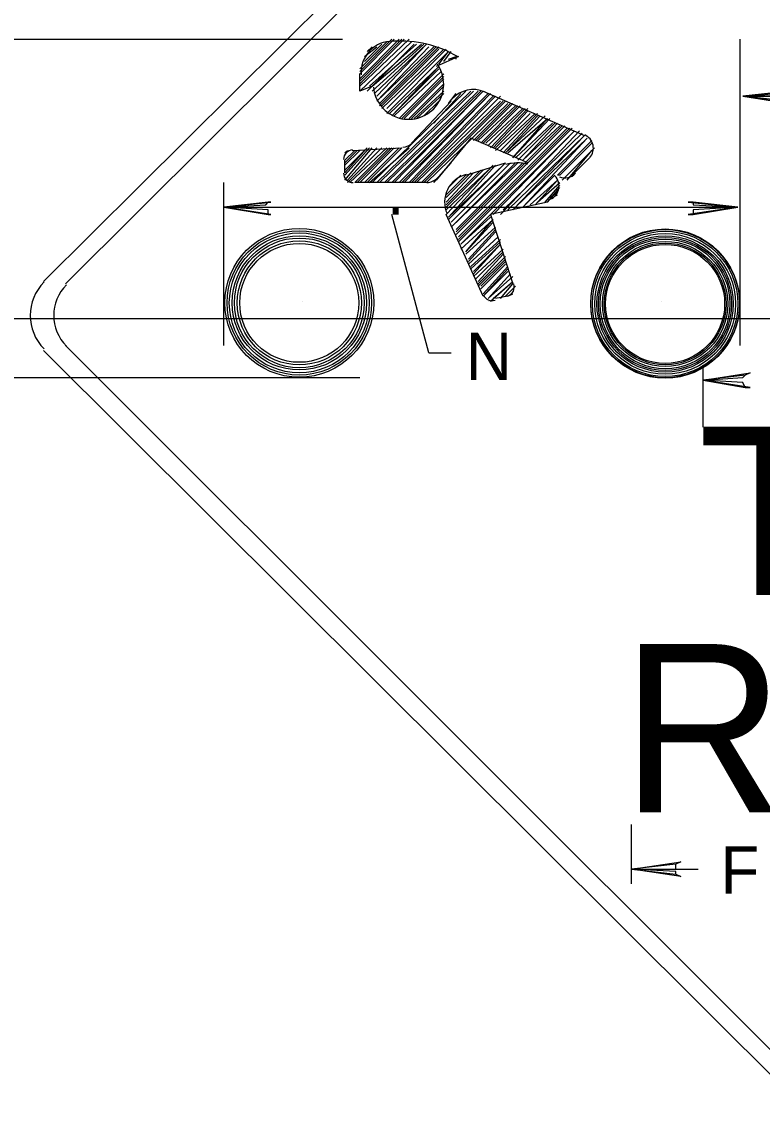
# Model space of a CAD drawing. Extents: x -0.018 to 0.195, y -0.006 to 0.263.
# Drawn here: x 0.0462 to 0.0836, y 0.1098 to 0.1654 of the extents above; entities that cross this region are included whole.
import ezdxf

# ---------------------------------------------------------------- set-up
doc = ezdxf.new("R2010")
doc.units = 0
doc.layers.add('1', color=7, linetype='Continuous')
doc.layers.add('12', color=7, linetype='Continuous')

msp = doc.modelspace()

# ---------------------------------------------------------------- linework, layer by layer
at = {"layer": '1'}
for p, q in [((0.043625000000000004, 0.1645), (0.062375, 0.1645)), ((0.056375, 0.149), (0.056375, 0.15725)), ((0.056375, 0.156), (0.082375, 0.156)), ((0.032375, 0.150375), (0.143125, 0.150375)), ((0.025750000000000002, 0.147375), (0.06325, 0.147375))]:
    msp.add_line(p, q, dxfattribs=at)
msp.add_lwpolyline([(0.058625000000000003, 0.155625), (0.058625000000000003, 0.155875), (0.056375, 0.156), (0.058625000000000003, 0.155625), (0.058750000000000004, 0.155625), (0.056375, 0.156), (0.0585, 0.156125), (0.058625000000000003, 0.15625), (0.056375, 0.156), (0.058750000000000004, 0.15625), (0.058625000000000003, 0.15625)], dxfattribs=at)
at = {"layer": '12'}
for p, q in [((0.04725, 0.15225), (0.08637500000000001, 0.19112500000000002)), ((0.048375, 0.152125), (0.08650000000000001, 0.19012500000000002)), ((0.06325, 0.162875), (0.064875, 0.1645)), ((0.06325, 0.16275), (0.065, 0.1645)), ((0.06325, 0.1625), (0.06525, 0.1645)), ((0.06325, 0.162375), (0.065375, 0.1645)), ((0.06325, 0.16225), (0.0655, 0.1645)), ((0.06325, 0.162125), (0.06575, 0.1645)), ((0.06325, 0.163), (0.064625, 0.164375)), ((0.06325, 0.161875), (0.065875, 0.164375)), ((0.0635, 0.163375), (0.064375, 0.16425)), ((0.0635, 0.163625), (0.064125, 0.164125)), ((0.063625, 0.161875), (0.066, 0.16425)), ((0.063625, 0.163875), (0.063875, 0.164125)), ((0.06375, 0.162125), (0.066125, 0.16425)), ((0.063875, 0.162125), (0.066375, 0.16425)), ((0.063875, 0.161875), (0.0665, 0.16425)), ((0.064, 0.16175), (0.066625, 0.16425)), ((0.064125, 0.161625), (0.066625, 0.16425)), ((0.064125, 0.161375), (0.06675, 0.164125)), ((0.064125, 0.161375), (0.067, 0.164125)), ((0.06425, 0.16125), (0.067125, 0.164125)), ((0.06425, 0.161125), (0.06725, 0.164125)), ((0.0825, 0.149), (0.0825, 0.1645)), ((0.064375, 0.161125), (0.06725, 0.164)), ((0.064375, 0.161), (0.0675, 0.164)), ((0.064625, 0.161), (0.067625, 0.164)), ((0.064625, 0.16075), (0.06775, 0.163875)), ((0.06825, 0.163625), (0.067125, 0.163125)), ((0.06725, 0.16325), (0.06775, 0.163875)), ((0.0675, 0.163375), (0.067875, 0.163875)), ((0.06775, 0.1635), (0.068125, 0.163625)), ((0.068125, 0.163625), (0.06825, 0.163625)), ((0.068125, 0.1635), (0.068125, 0.163625)), ((0.06475, 0.16075), (0.06725, 0.163125)), ((0.064875, 0.160625), (0.06725, 0.163125)), ((0.064875, 0.160625), (0.06725, 0.163)), ((0.06325, 0.161875), (0.06325, 0.16275)), ((0.065, 0.160625), (0.067375, 0.162875)), ((0.06525, 0.1605), (0.0675, 0.16275)), ((0.065375, 0.1605), (0.0675, 0.162625)), ((0.0655, 0.1605), (0.0675, 0.1625)), ((0.063875, 0.162125), (0.06325, 0.161875)), ((0.063875, 0.15725), (0.068625, 0.161875)), ((0.064125, 0.15725), (0.068875, 0.161875)), ((0.06425, 0.15725), (0.069, 0.161875)), ((0.0645, 0.15725), (0.06925, 0.161875)), ((0.064625, 0.15725), (0.069375, 0.161875)), ((0.064875, 0.15725), (0.0695, 0.161875)), ((0.065, 0.15725), (0.0695, 0.161875)), ((0.06575, 0.1605), (0.0675, 0.16225)), ((0.065875, 0.1605), (0.0675, 0.162125)), ((0.066, 0.1605), (0.0675, 0.161875)), ((0.0695, 0.161875), (0.074625, 0.15962500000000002)), ((0.06525, 0.15725), (0.06975, 0.16175)), ((0.065375, 0.15725), (0.069875, 0.16175)), ((0.0655, 0.15725), (0.069875, 0.16175)), ((0.06575, 0.15725), (0.07, 0.161625)), ((0.065875, 0.15725), (0.070125, 0.161625)), ((0.065875, 0.15925), (0.067875, 0.161375)), ((0.066, 0.15725), (0.07037500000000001, 0.161625)), ((0.066125, 0.1605), (0.0675, 0.16175)), ((0.066125, 0.15725), (0.07037500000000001, 0.161375)), ((0.066375, 0.15725), (0.07050000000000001, 0.161375)), ((0.0665, 0.160625), (0.06725, 0.161375)), ((0.0665, 0.15725), (0.07062500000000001, 0.161375)), ((0.067, 0.16025), (0.068375, 0.16175)), ((0.06775, 0.16125), (0.068125, 0.16175)), ((0.082625, 0.161625), (0.088375, 0.161625)), ((0.066625, 0.15725), (0.07075000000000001, 0.16125)), ((0.069, 0.15937500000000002), (0.07087500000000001, 0.16125)), ((0.069125, 0.15937500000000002), (0.07100000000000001, 0.16125)), ((0.06925, 0.15937500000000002), (0.07112500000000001, 0.161125)), ((0.069375, 0.15925), (0.07125000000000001, 0.161125)), ((0.0695, 0.15925), (0.07137500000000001, 0.161125)), ((0.069625, 0.15925), (0.07150000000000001, 0.161)), ((0.06975, 0.15912500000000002), (0.07162500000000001, 0.161)), ((0.069875, 0.159), (0.07175000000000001, 0.161)), ((0.07, 0.159), (0.07175000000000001, 0.160875)), ((0.070125, 0.159), (0.07187500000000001, 0.16075)), ((0.070125, 0.15887500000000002), (0.072125, 0.16075)), ((0.07037500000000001, 0.15887500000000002), (0.07225, 0.16075)), ((0.07050000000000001, 0.15875), (0.07225, 0.160625)), ((0.07062500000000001, 0.15875), (0.072375, 0.160625)), ((0.07062500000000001, 0.15875), (0.072625, 0.160625)), ((0.07075000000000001, 0.15875), (0.07275, 0.1605)), ((0.07100000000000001, 0.1585), (0.07275, 0.1605)), ((0.07100000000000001, 0.1585), (0.072875, 0.1605)), ((0.07112500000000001, 0.1585), (0.073, 0.16025)), ((0.07125000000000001, 0.15837500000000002), (0.073125, 0.16025)), ((0.07150000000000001, 0.15837500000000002), (0.07325, 0.16025)), ((0.06825, 0.1545), (0.07375, 0.16)), ((0.06825, 0.154375), (0.073875, 0.16)), ((0.06825, 0.15425), (0.074, 0.16)), ((0.068375, 0.154125), (0.074125, 0.15987500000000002)), ((0.07, 0.155625), (0.074125, 0.15987500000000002)), ((0.07037500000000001, 0.155625), (0.074375, 0.15987500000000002)), ((0.07050000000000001, 0.155875), (0.0745, 0.15975)), ((0.07150000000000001, 0.15837500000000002), (0.073375, 0.160125)), ((0.07162500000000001, 0.15825), (0.0735, 0.160125)), ((0.07175000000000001, 0.15825), (0.073625, 0.160125)), ((0.068875, 0.1595), (0.067125, 0.15737500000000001)), ((0.068875, 0.1595), (0.068875, 0.1595)), ((0.068875, 0.1595), (0.068875, 0.1595)), ((0.07175000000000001, 0.15825), (0.068875, 0.1595)), ((0.07075000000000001, 0.155875), (0.074625, 0.15962500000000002)), ((0.07100000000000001, 0.155875), (0.074625, 0.15962500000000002)), ((0.07112500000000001, 0.156), (0.07475, 0.1595)), ((0.07150000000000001, 0.156), (0.07475, 0.1595)), ((0.07325, 0.15762500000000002), (0.075, 0.15937500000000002)), ((0.07325, 0.15762500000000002), (0.075, 0.15937500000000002)), ((0.073375, 0.15762500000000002), (0.075, 0.15925)), ((0.0625, 0.15775), (0.063625, 0.159)), ((0.0625, 0.15762500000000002), (0.06375, 0.159)), ((0.0625, 0.15737500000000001), (0.063875, 0.159)), ((0.0625, 0.15875), (0.062625, 0.15887500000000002)), ((0.0625, 0.15837500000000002), (0.063, 0.15887500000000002)), ((0.0625, 0.15825), (0.063125, 0.15887500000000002)), ((0.0625, 0.15812500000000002), (0.06325, 0.15887500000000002)), ((0.0625, 0.15787500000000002), (0.0635, 0.15887500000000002)), ((0.062625, 0.15737500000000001), (0.064125, 0.159)), ((0.062625, 0.15725), (0.064375, 0.159)), ((0.06275, 0.15725), (0.064625, 0.159)), ((0.062875, 0.15887500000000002), (0.065375, 0.159)), ((0.063, 0.15725), (0.06475, 0.159)), ((0.063, 0.15887500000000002), (0.063, 0.15887500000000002)), ((0.063125, 0.15725), (0.064875, 0.159)), ((0.06325, 0.15725), (0.065, 0.159)), ((0.0635, 0.15725), (0.06525, 0.159)), ((0.063625, 0.15725), (0.065375, 0.159)), ((0.06375, 0.15725), (0.06575, 0.159)), ((0.0735, 0.15737500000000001), (0.075125, 0.159)), ((0.07375, 0.15737500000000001), (0.075, 0.15887500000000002)), ((0.0625, 0.15775), (0.0625, 0.15837500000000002)), ((0.067, 0.15725), (0.067875, 0.15825)), ((0.067625, 0.155625), (0.07, 0.15812500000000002)), ((0.06775, 0.155375), (0.07062500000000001, 0.15825)), ((0.06775, 0.1555), (0.070125, 0.15812500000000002)), ((0.06775, 0.1555), (0.07050000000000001, 0.15812500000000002)), ((0.067875, 0.15525), (0.07087500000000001, 0.15825)), ((0.067875, 0.155), (0.07112500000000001, 0.15825)), ((0.067875, 0.155), (0.07125000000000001, 0.15825)), ((0.068125, 0.154875), (0.07150000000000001, 0.15825)), ((0.068125, 0.15475), (0.07162500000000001, 0.15825)), ((0.068125, 0.154625), (0.07175000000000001, 0.15825)), ((0.068625, 0.15762500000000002), (0.07062500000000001, 0.15825)), ((0.07150000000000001, 0.15837500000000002), (0.07150000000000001, 0.15837500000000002)), ((0.074, 0.15762500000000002), (0.074625, 0.15825)), ((0.074875, 0.1585), (0.074125, 0.15775)), ((0.067625, 0.156125), (0.069375, 0.15787500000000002)), ((0.067625, 0.156), (0.0695, 0.15787500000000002)), ((0.067625, 0.155875), (0.06975, 0.15787500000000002)), ((0.067625, 0.1565), (0.068875, 0.15775)), ((0.067625, 0.15625), (0.069, 0.15775)), ((0.067625, 0.15662500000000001), (0.068625, 0.15762500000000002)), ((0.06775, 0.157), (0.068375, 0.15762500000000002)), ((0.07162500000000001, 0.156125), (0.073125, 0.15762500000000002)), ((0.073375, 0.15762500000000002), (0.07325, 0.15762500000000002)), ((0.066625, 0.15725), (0.063, 0.15725)), ((0.067125, 0.15737500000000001), (0.067125, 0.15737500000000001)), ((0.07187500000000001, 0.156125), (0.07325, 0.15737500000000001)), ((0.072125, 0.156125), (0.07325, 0.15737500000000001)), ((0.07225, 0.15625), (0.073375, 0.15725)), ((0.072625, 0.15625), (0.073375, 0.15712500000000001)), ((0.07275, 0.15625), (0.073375, 0.157)), ((0.072875, 0.1565), (0.07325, 0.15675)), ((0.072875, 0.1565), (0.07325, 0.15675)), ((0.073, 0.1565), (0.07325, 0.15662500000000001)), ((0.07275, 0.15625), (0.069875, 0.155625)), ((0.06675, 0.148625), (0.064875, 0.155625)), ((0.0695, 0.1515), (0.067625, 0.155625)), ((0.068375, 0.154125), (0.069875, 0.1555)), ((0.068375, 0.153875), (0.07, 0.155375)), ((0.068625, 0.15375), (0.07, 0.155375)), ((0.068625, 0.15375), (0.07, 0.15525)), ((0.069875, 0.155625), (0.07100000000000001, 0.152125)), ((0.068625, 0.153625), (0.070125, 0.155)), ((0.06875, 0.153375), (0.070125, 0.154875)), ((0.06875, 0.15325), (0.070125, 0.15475)), ((0.06875, 0.15325), (0.070125, 0.15475)), ((0.06875, 0.153125), (0.07025, 0.1545)), ((0.068875, 0.153), (0.07037500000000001, 0.154375)), ((0.068875, 0.152875), (0.07037500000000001, 0.15425)), ((0.069, 0.15275), (0.07037500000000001, 0.154125)), ((0.069, 0.152625), (0.07037500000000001, 0.154125)), ((0.069, 0.1525), (0.07050000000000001, 0.153875)), ((0.069125, 0.152375), (0.07050000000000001, 0.15375)), ((0.06925, 0.15225), (0.07050000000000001, 0.153625)), ((0.06925, 0.152125), (0.07062500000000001, 0.1535)), ((0.06925, 0.152), (0.07062500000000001, 0.153375)), ((0.069375, 0.152), (0.07062500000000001, 0.15325)), ((0.069375, 0.151875), (0.07062500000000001, 0.153125)), ((0.0695, 0.151625), (0.07075000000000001, 0.153)), ((0.0695, 0.1515), (0.07075000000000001, 0.152875)), ((0.0695, 0.1515), (0.07075000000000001, 0.15275)), ((0.06975, 0.151375), (0.07087500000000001, 0.152625)), ((0.06975, 0.151375), (0.07100000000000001, 0.1525)), ((0.069875, 0.15125), (0.07100000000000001, 0.15225)), ((0.07, 0.151375), (0.07100000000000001, 0.15225)), ((0.07037500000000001, 0.151375), (0.07100000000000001, 0.152125)), ((0.07062500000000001, 0.1515), (0.07112500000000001, 0.152)), ((0.07075000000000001, 0.1515), (0.070125, 0.151375)), ((0.07075000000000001, 0.1515), (0.07100000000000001, 0.151625)), ((0.07075000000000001, 0.1515), (0.07075000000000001, 0.1515)), ((0.07100000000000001, 0.151625), (0.07100000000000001, 0.151625)), ((0.060375, 0.15125), (0.060375, 0.15125)), ((0.06975, 0.15125), (0.06975, 0.15125)), ((0.0785, 0.15125), (0.0785, 0.15125)), ((0.08637500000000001, 0.10975), (0.04725, 0.14875)), ((0.08650000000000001, 0.110875), (0.048375, 0.149)), ((0.06675, 0.148625), (0.067875, 0.148625)), ((0.080625, 0.144875), (0.080625, 0.148)), ((0.0825, 0.147375), (0.0825, 0.147375)), ((0.077, 0.12175), (0.077, 0.12475)), ((0.077, 0.1225), (0.080375, 0.1225))]:
    msp.add_line(p, q, dxfattribs=at)
for points in [[(0.085, 0.16125), (0.084875, 0.161375), (0.082625, 0.161625), (0.085, 0.16125), (0.085, 0.16125), (0.082625, 0.161625), (0.084875, 0.16175), (0.085, 0.161875), (0.082625, 0.161625), (0.085, 0.161875), (0.085, 0.161875)], [(0.080125, 0.15625), (0.080125, 0.156125), (0.082375, 0.156), (0.080125, 0.15625), (0.079875, 0.15625), (0.082375, 0.156), (0.080125, 0.155875), (0.080125, 0.155625), (0.082375, 0.156), (0.079875, 0.155625), (0.080125, 0.155625)], [(0.08275, 0.146875), (0.082625, 0.147125), (0.080625, 0.14725), (0.08275, 0.146875), (0.083, 0.146875), (0.080625, 0.14725), (0.082625, 0.147375), (0.08275, 0.1475), (0.080625, 0.14725), (0.083, 0.147625), (0.08275, 0.1475)], [(0.07925, 0.12225), (0.07925, 0.122375), (0.077, 0.1225), (0.07925, 0.12225), (0.0795, 0.122125), (0.077, 0.1225), (0.07925, 0.1225), (0.07925, 0.12275), (0.077, 0.1225), (0.0795, 0.122875), (0.07925, 0.12275)]]:
    msp.add_lwpolyline(points, dxfattribs=at)
for centre, radius in [((0.060193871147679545, 0.15116092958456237), 0.0037659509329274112), ((0.06019384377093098, 0.15116087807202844), 0.0036536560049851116), ((0.06019384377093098, 0.15116087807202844), 0.00353950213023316), ((0.0787023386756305, 0.15113413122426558), 0.0037659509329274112), ((0.07870271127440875, 0.15110688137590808), 0.003763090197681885), ((0.07870271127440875, 0.15110688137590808), 0.003677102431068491), ((0.07870271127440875, 0.15110688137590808), 0.0035619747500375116), ((0.06019384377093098, 0.15116087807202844), 0.003398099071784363), ((0.06019384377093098, 0.15116087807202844), 0.0032824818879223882), ((0.06019384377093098, 0.15116087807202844), 0.0031400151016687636), ((0.06019384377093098, 0.15116087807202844), 0.0030100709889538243), ((0.07870271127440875, 0.15110688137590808), 0.0034488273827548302), ((0.07870271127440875, 0.15110688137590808), 0.003364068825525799), ((0.07870271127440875, 0.15110688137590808), 0.003279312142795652), ((0.07870271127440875, 0.15110688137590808), 0.0031649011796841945), ((0.07870271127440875, 0.15110688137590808), 0.0030794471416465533), ((0.07870271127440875, 0.15110688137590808), 0.0030100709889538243)]:
    msp.add_circle(centre, radius, dxfattribs=at)
for centre, radius, start, end in [((0.06489273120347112, 0.1628314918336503), 0.001570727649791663, 88.48155, 184.50301666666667), ((0.06530226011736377, 0.15868211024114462), 0.005731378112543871, 59.344427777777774, 93.68043888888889), ((0.06571896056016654, 0.1622307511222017), 0.0017806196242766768, 184.73358055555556, 34.57944444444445), ((0.06899869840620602, 0.1605206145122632), 0.0014399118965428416, 66.67193611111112, 137.9205527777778), ((0.07435235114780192, 0.15899680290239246), 0.0007199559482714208, 317.92507222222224, 66.6723527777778), ((0.06539745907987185, 0.1597550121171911), 0.0007199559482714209, 273.0687638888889, 317.92113333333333), ((0.06291487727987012, 0.15842014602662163), 0.00047997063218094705, 93.07155277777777, 180), ((0.07122987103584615, 0.155842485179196), 0.0023998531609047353, 77.2352, 104.29543333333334), ((0.06291487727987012, 0.15773047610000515), 0.00047997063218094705, 180, 270), ((0.06664650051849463, 0.1579704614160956), 0.0007199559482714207, 270, 318.1571388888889), ((0.06898514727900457, 0.15626129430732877), 0.0014399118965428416, 104.30228055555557, 204.00179722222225), ((0.07261697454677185, 0.15707429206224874), 0.0007199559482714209, 284.30085277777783, 45.51350277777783), ((0.073635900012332, 0.15820291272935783), 0.0007199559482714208, 246.68698888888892, 317.90093611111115), ((0.048981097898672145, 0.15052355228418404), 0.002399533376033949, 135.00000000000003, 225.00000000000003), ((0.049970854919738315, 0.15052355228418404), 0.0021995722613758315, 135, 225), ((0.07059346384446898, 0.15197149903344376), 0.0004799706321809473, 288.85433611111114, 18.416838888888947), ((0.06994334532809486, 0.15174952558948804), 0.00047997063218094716, 203.99310277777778, 288.8420277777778)]:
    msp.add_arc(centre, radius, start, end, dxfattribs=at)

# ---------------------------------------------------------------- texts
for s, height, p in [('.', 0.00239925, (0.064625, 0.155625)), ('N', 0.00239925, (0.068625, 0.14725)), ('THE', 0.008517, (0.080375, 0.136375)), ('ROAD', 0.008517, (0.0765, 0.12537500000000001)), ('F', 0.00239925, (0.0815, 0.12125))]:
    msp.add_text(s, height=height, dxfattribs=at).set_placement(p)

doc.saveas('drawing.dxf')
